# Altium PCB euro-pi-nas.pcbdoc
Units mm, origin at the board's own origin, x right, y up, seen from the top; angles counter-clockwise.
Board outline 172.7 x 115.7 mm, 2 copper layers (Top Layer, Bottom Layer); 4 components, 0 nets, 4 pads, 0 vias.
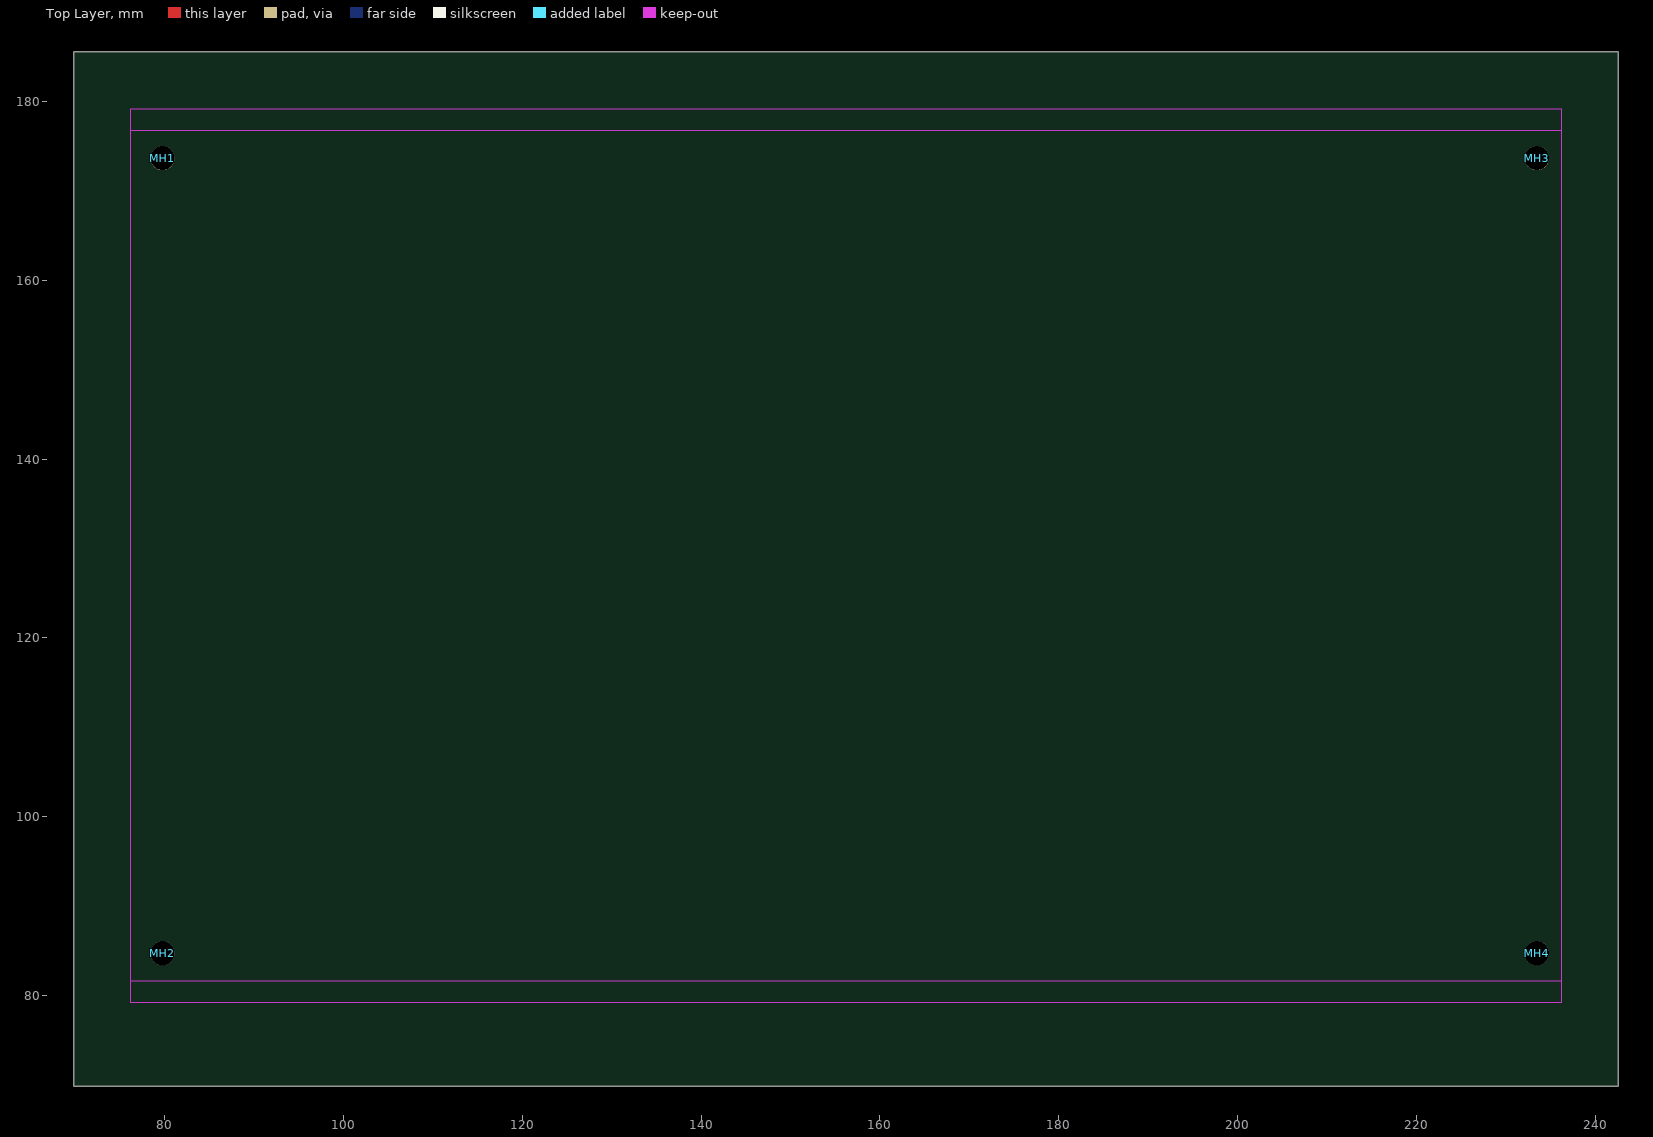
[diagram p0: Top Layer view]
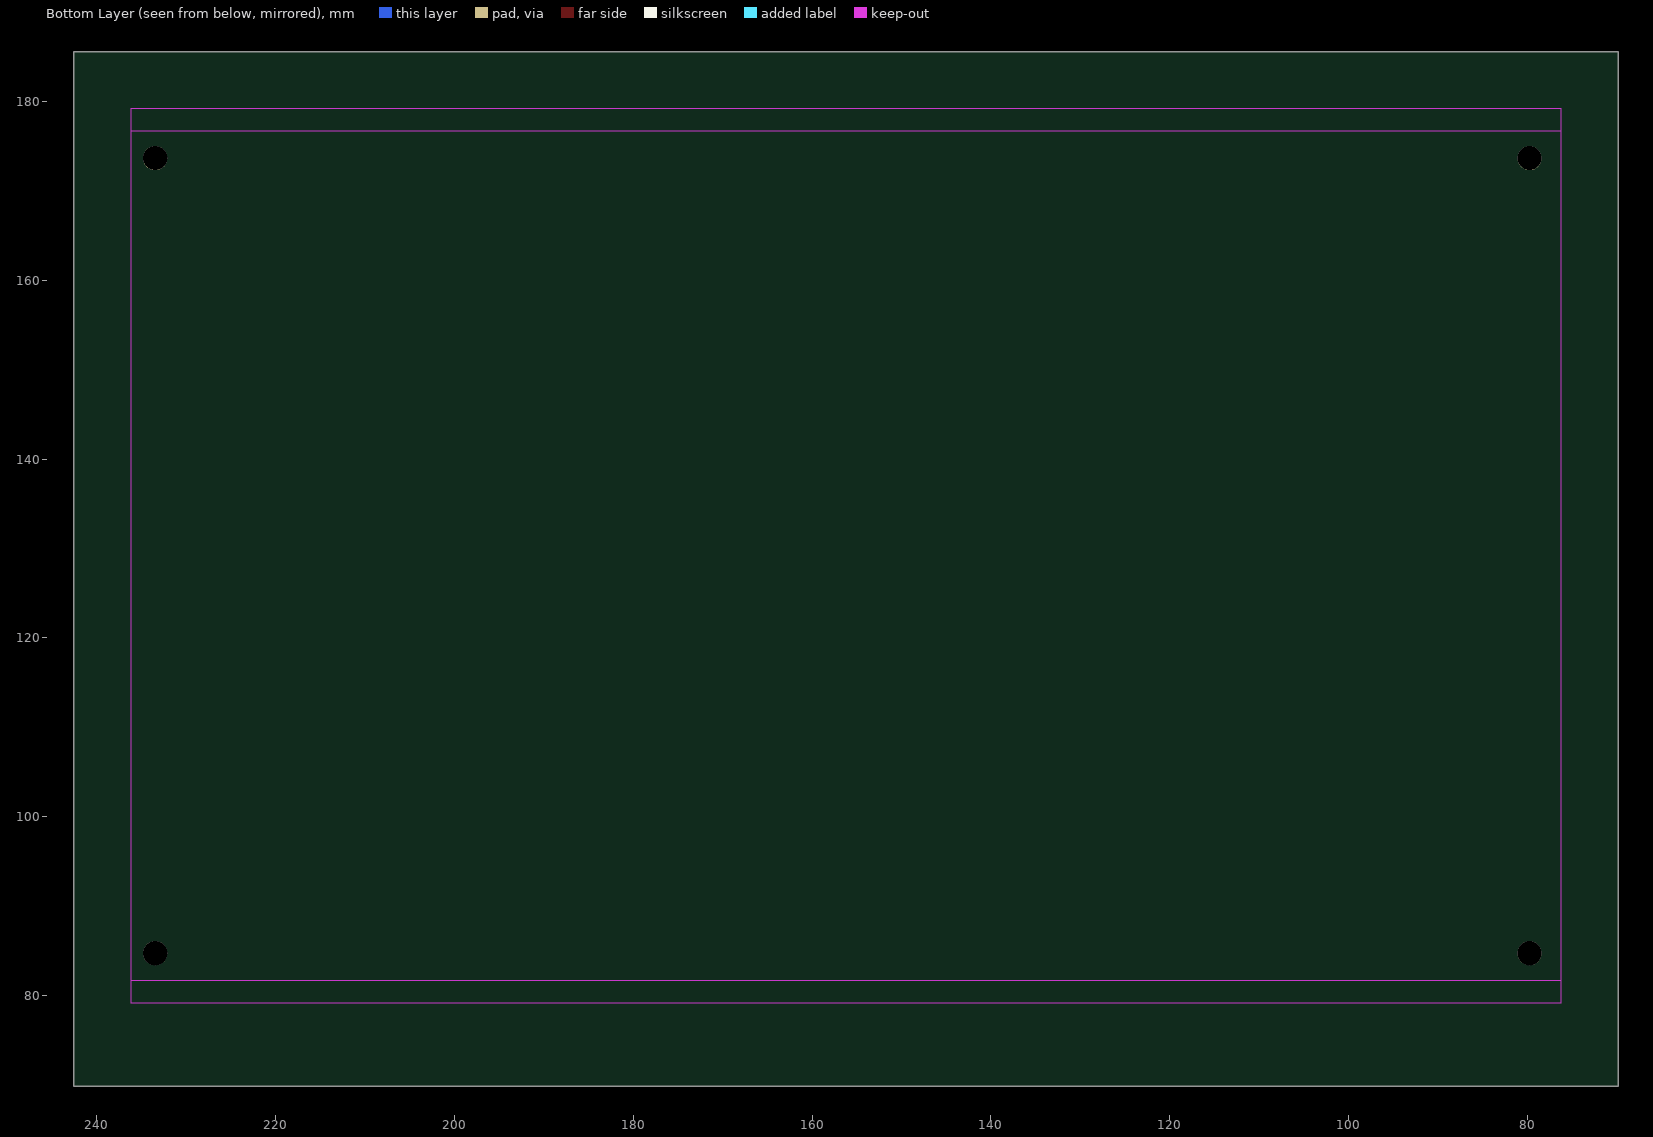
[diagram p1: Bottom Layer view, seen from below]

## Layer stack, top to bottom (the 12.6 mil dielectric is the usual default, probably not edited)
Top Layer: signal copper (thickness not stored)
Dielectric: dielectric 0.32, FR-4, Dk 4.8
Bottom Layer: signal copper (thickness not stored)

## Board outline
242.55,69.85 69.85,69.85 69.85,185.55 242.55,185.55

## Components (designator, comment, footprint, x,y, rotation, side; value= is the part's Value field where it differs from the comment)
MH1 "MountingHole_2.7mm_M2.5_DIN965" MountingHole:MountingHole_2.7mm_M2.5_DIN965 79.77,173.65 r0 top
MH2 "MountingHole_2.7mm_M2.5_DIN965" MountingHole:MountingHole_2.7mm_M2.5_DIN965 79.77,84.75 r0 top
MH3 "MountingHole_2.7mm_M2.5_DIN965" MountingHole:MountingHole_2.7mm_M2.5_DIN965 233.44,173.65 r0 top
MH4 "MountingHole_2.7mm_M2.5_DIN965" MountingHole:MountingHole_2.7mm_M2.5_DIN965 233.44,84.75 r0 top

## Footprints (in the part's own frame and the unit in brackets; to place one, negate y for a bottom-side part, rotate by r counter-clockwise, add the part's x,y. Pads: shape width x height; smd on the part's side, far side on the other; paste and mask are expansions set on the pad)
MountingHole:MountingHole_2.7mm_M2.5_DIN965 [mm]
  round 2.7 hole 2.7 unplated: 1(0,0)

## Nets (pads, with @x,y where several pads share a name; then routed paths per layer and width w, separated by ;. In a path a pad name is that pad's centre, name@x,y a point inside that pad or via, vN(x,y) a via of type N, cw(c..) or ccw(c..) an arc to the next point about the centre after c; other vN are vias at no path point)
pads on no net: MH1.1 MH2.1 MH3.1 MH4.1

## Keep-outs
Top Layer:
  region: 236.2,79.2 76.2,79.2 76.2,81.7 236.2,81.7
  region: 236.2,176.7 76.2,176.7 76.2,179.2 236.2,179.2
Bottom Layer:
  region: 236.2,79.2 76.2,79.2 76.2,81.7 236.2,81.7
  region: 236.2,176.7 76.2,176.7 76.2,179.2 236.2,179.2
Board Outline Layer:
  lines w0.025: 76.2,79.2 236.2,79.2 236.2,179.2 76.2,179.2 76.2,79.2

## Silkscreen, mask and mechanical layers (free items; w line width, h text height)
Mech6:
  text "Mounting holes are optional /  Keepout areas are for for guide rails" at 74.309,76.347 h0.72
